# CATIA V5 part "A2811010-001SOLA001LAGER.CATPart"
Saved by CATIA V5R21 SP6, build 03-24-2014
Part number: A2811010-001SOLA001LAGER
Revision: --A
Definition: A2811010-001SOLA001.LAGER
Source: made
Description: START_SOLV5_EF2000______
Property "PTC_WM_NAME": "A2811010-001SOLA001.LAGER"
Property "PTC_WM_NUMBER": "A2811010-001SOLA001LAGER"
Property "PTC_WM_REVISION": "--A"
Property "PTC_WM_INIT_REV": "01"
Bounding box of the stored display mesh (mm): x -28 to 28, y -28 to 28, z 0 to 20
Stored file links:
  J:\Transfer\Fueller Werkstudent\Stellungen\A2811010-001SOLA001LAGER.CATPart
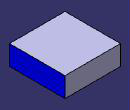
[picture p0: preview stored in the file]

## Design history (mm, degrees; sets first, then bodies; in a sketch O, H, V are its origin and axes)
AxisSystem1: origin (0, 0, 0), X (1, 0, 0), Y (0, 1, 0), Z (0, 0, 1)
Body1 (main body)
  Body2 "Positive"
    Sketch1 on xy-plane, origin (0, 0, 0), H (1, 0, 0), V (0, 1, 0)
      line L1 (-28, 28) -> (28, 28)
      line L2 (28, 28) -> (28, -28)
      line L3 (28, -28) -> (-28, -28)
      line L4 (-28, -28) -> (-28, 28)
      length L1 = 56
      length L2 = 56
      horizontal: L1 H, L3 H
      vertical: L2 V, L4 V
      symmetry: L4 L2 V, L1 L3 H
    Pad1: profile Sketch1, direction (0, 0, 1), length 20
  Assemble1: tool Body2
